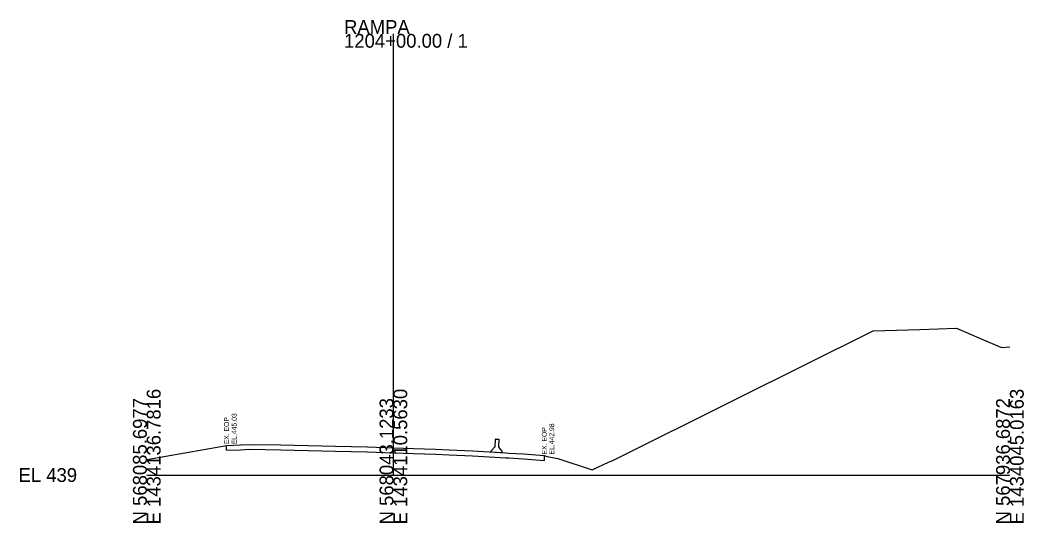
# Model space of a CAD drawing. Extents: x 1431908 to 1449087, y 567604 to 577825.
# Drawn here: x 1431908 to 1432111.5, y 575352.5 to 575454.4 of the extents above; entities that cross this region are included whole.
import ezdxf

# ---------------------------------------------------------------- set-up
doc = ezdxf.new("R2010")
doc.units = 0
for name, color, linetype in [('DESIGN - SHEET - Light Grid', 7, 'Continuous'), ('DESIGN - TYPICAL - Finished Grade and Subgrade', 7, 'Continuous'), ('SURVEY - GROUND - Existing Pavement Layer', 7, 'Continuous'), ('SURVEY - GROUND - Existing Pavement Text', 7, 'Continuous'), ('SURVEY - GROUND - Top of Ground', 7, 'Continuous')]:
    doc.layers.add(name, color=color, linetype=linetype)

msp = doc.modelspace()

# ---------------------------------------------------------------- linework, layer by layer
at = {"layer": 'DESIGN - SHEET - Light Grid'}
for p, q in [((1431983.66, 575362.16), (1431983.66, 575451.56)), ((1431933.66, 575362.16), (1431983.66, 575362.16)), ((1431983.66, 575362.16), (1432108.66, 575362.16))]:
    msp.add_line(p, q, dxfattribs=at)
at = {"layer": 'DESIGN - TYPICAL - Finished Grade and Subgrade'}
for p, q in [((1432004.29, 575367.91), (1432004.38, 575369.36)), ((1432004.48, 575369.46), (1432005.13, 575369.42)), ((1432005.04, 575367.87), (1432005.13, 575369.42)), ((1432003.48, 575366.95), (1432003.49, 575367.06)), ((1432003.52, 575367.13), (1432004.26, 575367.85)), ((1432003.57, 575366.85), (1432005.62, 575366.72)), ((1432005.71, 575367), (1432005.06, 575367.8)), ((1432005.72, 575366.82), (1432005.73, 575366.93))]:
    msp.add_line(p, q, dxfattribs=at)
for centre, start, end in [((1432004.48, 575369.36), 86.4785, 176.4785), ((1432003.58, 575366.95), 176.4785, 266.4785), ((1432003.58, 575367.06), 134.0314, 176.4785), ((1432004.19, 575367.92), 314.0314, 356.4785), ((1432005.14, 575367.86), 176.4785, 218.9256), ((1432005.62, 575366.82), 266.4785, 356.4785), ((1432005.63, 575366.93), 356.4785, 38.9256)]:
    msp.add_arc(centre, 0.1, start, end, dxfattribs=at)
at = {"layer": 'SURVEY - GROUND - Existing Pavement Layer'}
for p, q in [((1431949.83, 575367.18), (1431949.83, 575368.18)), ((1431949.83, 575367.18), (1431952.69, 575367.3)), ((1431952.69, 575367.3), (1431954.54, 575367.38)), ((1431954.54, 575367.38), (1431960.83, 575367.26)), ((1431960.83, 575367.26), (1431966.4, 575367.15)), ((1431966.4, 575367.15), (1431971.89, 575367.01)), ((1431971.89, 575367.01), (1431978.44, 575366.86)), ((1431978.44, 575366.86), (1431983.66, 575366.69)), ((1431983.66, 575366.69), (1431987.77, 575366.55)), ((1431987.77, 575366.55), (1431992.2, 575366.4)), ((1431992.2, 575366.4), (1431994.95, 575366.27)), ((1431994.95, 575366.27), (1431999.7, 575366.04)), ((1431999.7, 575366.04), (1432006.46, 575365.67)), ((1432006.46, 575365.67), (1432007.06, 575365.63)), ((1432007.06, 575365.63), (1432010.04, 575365.43)), ((1432010.04, 575365.43), (1432014.26, 575365.13)), ((1432014.26, 575366.13), (1432014.26, 575365.13))]:
    msp.add_line(p, q, dxfattribs=at)
at = {"layer": 'SURVEY - GROUND - Top of Ground'}
msp.add_lwpolyline([(1431933.66, 575365.28), (1431945.25, 575367.37), (1431949.83, 575368.18), (1431952.69, 575368.3), (1431954.54, 575368.38), (1431960.83, 575368.26), (1431966.4, 575368.15), (1431971.89, 575368.01), (1431978.44, 575367.86), (1431983.66, 575367.69), (1431987.77, 575367.55), (1431992.2, 575367.4), (1431994.95, 575367.27), (1431999.7, 575367.04), (1432006.46, 575366.67), (1432007.06, 575366.63), (1432010.04, 575366.43), (1432014.26, 575366.13), (1432014.83, 575365.94), (1432017.02, 575365.52), (1432023.96, 575363.19), (1432027.27, 575364.75), (1432028.12, 575365.14), (1432052.98, 575377.46), (1432080.93, 575391.36), (1432090.37, 575391.66), (1432097.8, 575391.96), (1432102.86, 575389.77), (1432106.93, 575387.98), (1432108.66, 575388.14)], dxfattribs=at)

# ---------------------------------------------------------------- texts
at = {"layer": 'DESIGN - SHEET - Light Grid'}
for s, p in [('RAMPA', (1431973.66, 575451.56)), ('1204+00.00 / 1', (1431973.66, 575448.76)), ('EL 439', (1431907.66, 575360.76))]:
    msp.add_text(s, height=2.8, dxfattribs=at).set_placement(p)
for s, p in [('E 1434136.7816', (1431936.46, 575352.16)), ('E 1434110.5630', (1431986.46, 575352.16)), ('E 1434045.0163', (1432111.46, 575352.16)), ('N 568085.6977', (1431933.66, 575352.16)), ('N 568043.1233', (1431983.66, 575352.16)), ('N 567936.6872', (1432108.66, 575352.16))]:
    msp.add_text(s, height=2.8, rotation=90, dxfattribs=at).set_placement(p)
at = {"layer": 'SURVEY - GROUND - Existing Pavement Text'}
for s, p in [('EX. EOP', (1431950.33, 575368.38)), ('EL.445.03', (1431951.87, 575368.38)), ('EX. EOP', (1432014.76, 575366.33)), ('EL.442.98', (1432016.26, 575366.33))]:
    msp.add_text(s, height=1, rotation=90, dxfattribs=at).set_placement(p)

doc.saveas('drawing.dxf')
